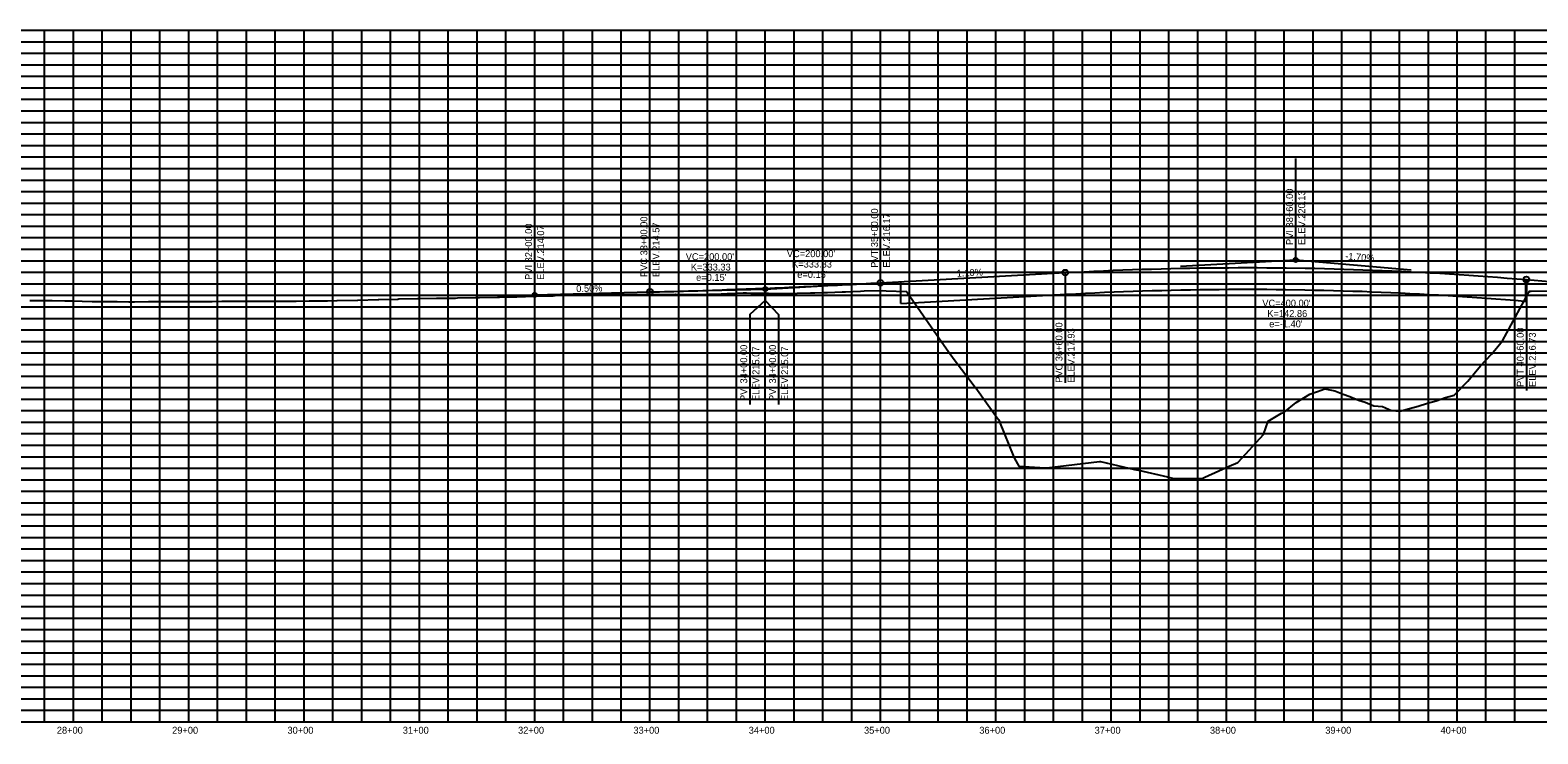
# Model space of a CAD drawing. Extents: x 1732967 to 1742744, y 374025 to 374739.
# Drawn here: x 1735020 to 1736327, y 374119 to 374730 of the extents above; entities that cross this region are included whole.
import ezdxf

# ---------------------------------------------------------------- set-up
doc = ezdxf.new("R2010")
doc.units = 0
for name, color, linetype in [('R_Axis_Annotation', 7, 'Continuous'), ('R_Draft', 7, 'Continuous'), ('R_Exist Surface', 7, 'Continuous'), ('R_Grid', 7, 'Continuous'), ('R_Grid_Minor', 7, 'Continuous'), ('R_Vert Alg', 7, 'Continuous'), ('R_Vert Alg Annot', 7, 'Continuous')]:
    doc.layers.add(name, color=color, linetype=linetype)

msp = doc.modelspace()

# ---------------------------------------------------------------- linework, layer by layer
at = {"layer": 'R_Draft'}
for p, q in [((1735774.6, 374492.6), (1735774.6, 374511.4)), ((1736316.7, 374494.5), (1736316.7, 374513.3)), ((1735774.6, 374492.6), (1735918.2, 374500.5)), ((1736315.6, 374494.6), (1736316.7, 374494.5))]:
    msp.add_line(p, q, dxfattribs=at)
msp.add_lwpolyline([(1735918.2, 374500.5), (1735926.5, 374501), (1735934.8, 374501.4), (1735943, 374501.8), (1735951.3, 374502.2), (1735959.6, 374502.5), (1735967.9, 374502.8), (1735976.1, 374503.1), (1735984.4, 374503.4), (1735992.7, 374503.7), (1736001, 374503.9), (1736009.3, 374504.1), (1736017.5, 374504.3), (1736025.8, 374504.4), (1736034.1, 374504.6), (1736042.4, 374504.7), (1736050.7, 374504.7), (1736058.9, 374504.8), (1736067.2, 374504.8), (1736075.5, 374504.8), (1736083.8, 374504.8), (1736092, 374504.8), (1736100.3, 374504.7), (1736108.6, 374504.6), (1736125.2, 374504.4), (1736133.4, 374504.2), (1736141.7, 374504), (1736150, 374503.8), (1736158.3, 374503.6), (1736166.6, 374503.3), (1736174.8, 374503.1), (1736183.1, 374502.7), (1736191.4, 374502.4), (1736199.7, 374502.1), (1736208, 374501.7), (1736216.2, 374501.3), (1736224.5, 374500.9), (1736232.8, 374500.4), (1736241.1, 374499.9), (1736249.3, 374499.4), (1736257.6, 374498.9), (1736265.9, 374498.4), (1736274.2, 374497.8), (1736282.5, 374497.2), (1736290.7, 374496.6), (1736299, 374495.9), (1736307.3, 374495.3), (1736315.6, 374494.6)], dxfattribs=at)
at = {"layer": 'R_Exist Surface'}
msp.add_lwpolyline([(1735019.5, 374495.2), (1735020.3, 374495.2), (1735021.1, 374495.2), (1735034.6, 374495.1), (1735038, 374495.1), (1735038.7, 374495.1), (1735049.8, 374494.9), (1735055.7, 374494.7), (1735056.1, 374494.7), (1735064.9, 374494.5), (1735073.4, 374494.3), (1735073.5, 374494.3), (1735077.7, 374494.3), (1735080, 374494.3), (1735089.6, 374494.1), (1735095.2, 374494.1), (1735105.1, 374493.9), (1735105.7, 374493.9), (1735110.3, 374494), (1735122.2, 374494.1), (1735122.8, 374494.1), (1735123.5, 374494.1), (1735125.5, 374494.1), (1735140, 374494.2), (1735140.6, 374494.2), (1735140.9, 374494.2), (1735155.7, 374494.3), (1735158.8, 374494.3), (1735170.9, 374494.3), (1735176.5, 374494.3), (1735177.5, 374494.3), (1735186, 374494.4), (1735195, 374494.5), (1735195.8, 374494.5), (1735196.6, 374494.5), (1735201.2, 374494.5), (1735214.1, 374494.6), (1735214.7, 374494.6), (1735216.3, 374494.6), (1735231.4, 374494.6), (1735232.1, 374494.6), (1735232.6, 374494.6), (1735246.6, 374494.6), (1735250, 374494.6), (1735250.4, 374494.6), (1735261.7, 374494.7), (1735267.9, 374494.8), (1735268, 374494.8), (1735276.9, 374494.9), (1735277.4, 374494.9), (1735285.6, 374495), (1735285.8, 374495), (1735303.5, 374495.4), (1735303.9, 374495.4), (1735321.4, 374495.9), (1735322, 374495.9), (1735338.5, 374496.3), (1735339.4, 374496.4), (1735355.5, 374496.8), (1735356.7, 374496.9), (1735372.1, 374497), (1735373.5, 374497.1), (1735388.6, 374497.2), (1735390.2, 374497.3), (1735405.9, 374497.6), (1735407.6, 374497.7), (1735409.4, 374497.7), (1735425, 374498), (1735426.8, 374498.1), (1735441.8, 374498.4), (1735456.8, 374498.8), (1735458.5, 374498.8), (1735473.3, 374499.2), (1735474.9, 374499.3), (1735489.7, 374499.7), (1735491.3, 374499.8), (1735506.4, 374500), (1735507.8, 374500), (1735523.1, 374500.3), (1735524.3, 374500.3), (1735525.3, 374500.3), (1735537.2, 374500.4), (1735538.5, 374500.4), (1735552.3, 374500.4), (1735564.3, 374500.4), (1735565.9, 374500.4), (1735578.1, 374500.4), (1735579.4, 374500.5), (1735591.2, 374500.4), (1735592.2, 374500.4), (1735604.1, 374500.4), (1735608, 374500.4), (1735608.6, 374500.5), (1735613.7, 374500.7), (1735624.1, 374501.2), (1735627, 374501.2), (1735638.1, 374501.7), (1735640.8, 374501.6), (1735644.6, 374501.5), (1735656.6, 374501.4), (1735660.1, 374501.4), (1735671.8, 374501.2), (1735681.7, 374501.3), (1735684.8, 374501.4), (1735696.4, 374501.6), (1735698.8, 374501.7), (1735700.1, 374501.7), (1735708, 374501.9), (1735711, 374502), (1735724, 374502.5), (1735726.7, 374502.6), (1735739.9, 374503.2), (1735742.8, 374503.4), (1735758.9, 374503.8), (1735761.9, 374503.5), (1735779.7, 374502.9), (1735780.6, 374501.7), (1735814.3, 374453.2), (1735817.7, 374448.3), (1735817.8, 374448.2), (1735818, 374448), (1735821.1, 374443.9), (1735839.1, 374420), (1735839.7, 374419.2), (1735858.2, 374393.3), (1735859.6, 374391.7), (1735859.7, 374391.7), (1735860.4, 374389.9), (1735872.7, 374359.3), (1735873.2, 374357.9), (1735877, 374351.3), (1735895.2, 374350.3), (1735901.8, 374349.9), (1735903.8, 374350.1), (1735946.9, 374355.4), (1735948, 374355.5), (1735977.5, 374348.5), (1735980.9, 374347.8), (1736006.1, 374342), (1736009.1, 374341.3), (1736011.4, 374340.8), (1736036.5, 374341), (1736038.4, 374341.8), (1736059.4, 374351.3), (1736066.9, 374354.7), (1736067.4, 374354.9), (1736067.7, 374355.2), (1736089.3, 374378.8), (1736093.4, 374390.4), (1736105, 374397.4), (1736107, 374397.8), (1736117.5, 374406.5), (1736129.4, 374413.7), (1736136, 374416.1), (1736142.5, 374418.5), (1736151.2, 374416.6), (1736158.2, 374413.7), (1736164.2, 374411.8), (1736171.6, 374408.7), (1736177.3, 374407), (1736184.9, 374403.7), (1736192.5, 374403.2), (1736200.3, 374399.8), (1736207.5, 374399.2), (1736215.8, 374401.4), (1736223.5, 374403.4), (1736231.4, 374406.1), (1736239.1, 374408.2), (1736247, 374410.9), (1736254.7, 374412.9), (1736266.4, 374425.1), (1736277.3, 374438.3), (1736286.9, 374448.5), (1736296.4, 374460), (1736319.1, 374501.8), (1736319.7, 374502.4), (1736319.9, 374503.3), (1736321.4, 374503.3), (1736342, 374503.6)], dxfattribs=at)
at = {"layer": 'R_Grid'}
for p, q in [((1734257.2, 374729.6), (1737057.2, 374729.6)), ((1734257.2, 374729.6), (1737057.2, 374729.6)), ((1735057.2, 374129.6), (1735057.2, 374729.6)), ((1735157.2, 374129.6), (1735157.2, 374729.6)), ((1735257.2, 374129.6), (1735257.2, 374729.6)), ((1735357.2, 374129.6), (1735357.2, 374729.6)), ((1735457.2, 374129.6), (1735457.2, 374729.6)), ((1735557.2, 374129.6), (1735557.2, 374729.6)), ((1735657.2, 374129.6), (1735657.2, 374729.6)), ((1735757.2, 374129.6), (1735757.2, 374729.6)), ((1735857.2, 374129.6), (1735857.2, 374729.6)), ((1735957.2, 374129.6), (1735957.2, 374729.6)), ((1736057.2, 374129.6), (1736057.2, 374729.6)), ((1736157.2, 374129.6), (1736157.2, 374729.6)), ((1736257.2, 374129.6), (1736257.2, 374729.6)), ((1734257.2, 374679.6), (1737057.2, 374679.6)), ((1734257.2, 374629.6), (1737057.2, 374629.6)), ((1734257.2, 374579.6), (1737057.2, 374579.6)), ((1734257.2, 374529.6), (1737057.2, 374529.6)), ((1734257.2, 374479.6), (1737057.2, 374479.6)), ((1734257.2, 374429.6), (1737057.2, 374429.6)), ((1734257.2, 374379.6), (1737057.2, 374379.6)), ((1734257.2, 374329.6), (1737057.2, 374329.6)), ((1734257.2, 374279.6), (1737057.2, 374279.6)), ((1734257.2, 374229.6), (1737057.2, 374229.6)), ((1734257.2, 374179.6), (1737057.2, 374179.6)), ((1734257.2, 374129.6), (1737057.2, 374129.6))]:
    msp.add_line(p, q, dxfattribs=at)
at = {"layer": 'R_Grid_Minor'}
for p, q in [((1735032.2, 374129.6), (1735032.2, 374729.6)), ((1735082.2, 374129.6), (1735082.2, 374729.6)), ((1735107.2, 374129.6), (1735107.2, 374729.6)), ((1735132.2, 374129.6), (1735132.2, 374729.6)), ((1735182.2, 374129.6), (1735182.2, 374729.6)), ((1735207.2, 374129.6), (1735207.2, 374729.6)), ((1735232.2, 374129.6), (1735232.2, 374729.6)), ((1735282.2, 374129.6), (1735282.2, 374729.6)), ((1735307.2, 374129.6), (1735307.2, 374729.6)), ((1735332.2, 374129.6), (1735332.2, 374729.6)), ((1735382.2, 374129.6), (1735382.2, 374729.6)), ((1735407.2, 374129.6), (1735407.2, 374729.6)), ((1735432.2, 374129.6), (1735432.2, 374729.6)), ((1735482.2, 374129.6), (1735482.2, 374729.6)), ((1735507.2, 374129.6), (1735507.2, 374729.6)), ((1735532.2, 374129.6), (1735532.2, 374729.6)), ((1735582.2, 374129.6), (1735582.2, 374729.6)), ((1735607.2, 374129.6), (1735607.2, 374729.6)), ((1735632.2, 374129.6), (1735632.2, 374729.6)), ((1735682.2, 374129.6), (1735682.2, 374729.6)), ((1735707.2, 374129.6), (1735707.2, 374729.6)), ((1735732.2, 374129.6), (1735732.2, 374729.6)), ((1735782.2, 374129.6), (1735782.2, 374729.6)), ((1735807.2, 374129.6), (1735807.2, 374729.6)), ((1735832.2, 374129.6), (1735832.2, 374729.6)), ((1735882.2, 374129.6), (1735882.2, 374729.6)), ((1735907.2, 374129.6), (1735907.2, 374729.6)), ((1735932.2, 374129.6), (1735932.2, 374729.6)), ((1735982.2, 374129.6), (1735982.2, 374729.6)), ((1736007.2, 374129.6), (1736007.2, 374729.6)), ((1736032.2, 374129.6), (1736032.2, 374729.6)), ((1736082.2, 374129.6), (1736082.2, 374729.6)), ((1736107.2, 374129.6), (1736107.2, 374729.6)), ((1736132.2, 374129.6), (1736132.2, 374729.6)), ((1736182.2, 374129.6), (1736182.2, 374729.6)), ((1736207.2, 374129.6), (1736207.2, 374729.6)), ((1736232.2, 374129.6), (1736232.2, 374729.6)), ((1736282.2, 374129.6), (1736282.2, 374729.6)), ((1736307.2, 374129.6), (1736307.2, 374729.6)), ((1734257.2, 374719.6), (1737057.2, 374719.6)), ((1734257.2, 374709.6), (1737057.2, 374709.6)), ((1734257.2, 374699.6), (1737057.2, 374699.6)), ((1734257.2, 374689.6), (1737057.2, 374689.6)), ((1734257.2, 374669.6), (1737057.2, 374669.6)), ((1734257.2, 374659.6), (1737057.2, 374659.6)), ((1734257.2, 374649.6), (1737057.2, 374649.6)), ((1734257.2, 374639.6), (1737057.2, 374639.6)), ((1734257.2, 374619.6), (1737057.2, 374619.6)), ((1734257.2, 374609.6), (1737057.2, 374609.6)), ((1734257.2, 374599.6), (1737057.2, 374599.6)), ((1734257.2, 374589.6), (1737057.2, 374589.6)), ((1734257.2, 374569.6), (1737057.2, 374569.6)), ((1734257.2, 374559.6), (1737057.2, 374559.6)), ((1734257.2, 374549.6), (1737057.2, 374549.6)), ((1734257.2, 374539.6), (1737057.2, 374539.6)), ((1734257.2, 374519.6), (1737057.2, 374519.6)), ((1734257.2, 374509.6), (1737057.2, 374509.6)), ((1734257.2, 374499.6), (1737057.2, 374499.6)), ((1734257.2, 374489.6), (1737057.2, 374489.6)), ((1734257.2, 374469.6), (1737057.2, 374469.6)), ((1734257.2, 374459.6), (1737057.2, 374459.6)), ((1734257.2, 374449.6), (1737057.2, 374449.6)), ((1734257.2, 374439.6), (1737057.2, 374439.6)), ((1734257.2, 374419.6), (1737057.2, 374419.6)), ((1734257.2, 374409.6), (1737057.2, 374409.6)), ((1734257.2, 374399.6), (1737057.2, 374399.6)), ((1734257.2, 374389.6), (1737057.2, 374389.6)), ((1734257.2, 374369.6), (1737057.2, 374369.6)), ((1734257.2, 374359.6), (1737057.2, 374359.6)), ((1734257.2, 374349.6), (1737057.2, 374349.6)), ((1734257.2, 374339.6), (1737057.2, 374339.6)), ((1734257.2, 374319.6), (1737057.2, 374319.6)), ((1734257.2, 374309.6), (1737057.2, 374309.6)), ((1734257.2, 374299.6), (1737057.2, 374299.6)), ((1734257.2, 374289.6), (1737057.2, 374289.6)), ((1734257.2, 374269.6), (1737057.2, 374269.6)), ((1734257.2, 374259.6), (1737057.2, 374259.6)), ((1734257.2, 374249.6), (1737057.2, 374249.6)), ((1734257.2, 374239.6), (1737057.2, 374239.6)), ((1734257.2, 374219.6), (1737057.2, 374219.6)), ((1734257.2, 374209.6), (1737057.2, 374209.6)), ((1734257.2, 374199.6), (1737057.2, 374199.6)), ((1734257.2, 374189.6), (1737057.2, 374189.6)), ((1734257.2, 374169.6), (1737057.2, 374169.6)), ((1734257.2, 374159.6), (1737057.2, 374159.6)), ((1734257.2, 374149.6), (1737057.2, 374149.6)), ((1734257.2, 374139.6), (1737057.2, 374139.6))]:
    msp.add_line(p, q, dxfattribs=at)
at = {"layer": 'R_Vert Alg'}
for p, q in [((1735757.2, 374510.5), (1735917.2, 374519.3)), ((1736317.2, 374513.3), (1736337.2, 374511.6)), ((1735457.2, 374500), (1735557.2, 374502.5))]:
    msp.add_line(p, q, dxfattribs=at)
for points in [[(1735917.2, 374519.3), (1735925.5, 374519.7), (1735933.8, 374520.1), (1735942.2, 374520.5), (1735950.5, 374520.9), (1735958.8, 374521.3), (1735967.2, 374521.6), (1735975.5, 374521.9), (1735983.8, 374522.2), (1735992.2, 374522.4), (1736000.5, 374522.6), (1736008.8, 374522.8), (1736017.2, 374523), (1736025.5, 374523.2), (1736033.8, 374523.3), (1736042.2, 374523.4), (1736050.5, 374523.5), (1736058.8, 374523.5), (1736067.2, 374523.6), (1736075.5, 374523.6), (1736083.8, 374523.6), (1736092.2, 374523.5), (1736100.5, 374523.5), (1736108.8, 374523.4), (1736125.5, 374523.1), (1736133.8, 374523), (1736142.2, 374522.8), (1736150.5, 374522.6), (1736158.8, 374522.3), (1736167.2, 374522.1), (1736175.5, 374521.8), (1736183.8, 374521.5), (1736192.2, 374521.2), (1736200.5, 374520.8), (1736208.8, 374520.4), (1736217.2, 374520), (1736225.5, 374519.6), (1736233.8, 374519.1), (1736242.2, 374518.7), (1736250.5, 374518.2), (1736258.8, 374517.6), (1736267.2, 374517.1), (1736275.5, 374516.5), (1736283.8, 374515.9), (1736292.2, 374515.3), (1736300.5, 374514.6), (1736308.8, 374514), (1736317.2, 374513.3)], [(1735557.2, 374502.5), (1735561.3, 374502.6), (1735565.5, 374502.7), (1735569.7, 374502.8), (1735573.8, 374502.9), (1735578, 374503), (1735582.2, 374503.1), (1735586.3, 374503.3), (1735590.5, 374503.4), (1735594.7, 374503.5), (1735598.8, 374503.6), (1735603, 374503.8), (1735607.2, 374503.9), (1735611.3, 374504), (1735615.5, 374504.2), (1735619.7, 374504.3), (1735623.8, 374504.5), (1735628, 374504.6), (1735632.2, 374504.8), (1735636.3, 374504.9), (1735640.5, 374505.1), (1735644.7, 374505.2), (1735648.8, 374505.4), (1735653, 374505.5), (1735661.3, 374505.9), (1735665.5, 374506.1), (1735669.7, 374506.2), (1735673.8, 374506.4), (1735678, 374506.6), (1735682.2, 374506.8), (1735686.3, 374506.9), (1735690.5, 374507.1), (1735694.7, 374507.3), (1735698.8, 374507.5), (1735703, 374507.7), (1735707.2, 374507.9), (1735711.3, 374508.1), (1735715.5, 374508.3), (1735719.7, 374508.5), (1735723.8, 374508.7), (1735728, 374508.9), (1735732.2, 374509.1), (1735736.3, 374509.4), (1735740.5, 374509.6), (1735744.7, 374509.8), (1735748.8, 374510), (1735753, 374510.2), (1735757.2, 374510.5)]]:
    msp.add_lwpolyline(points, dxfattribs=at)
at = {"layer": 'R_Vert Alg Annot'}
for p, q in [((1736117.2, 374540.3), (1736117.2, 374618.3)), ((1735757.2, 374520.5), (1735757.2, 374598.5)), ((1735457.2, 374510), (1735457.2, 374588)), ((1735557.2, 374512.5), (1735557.2, 374590.5)), ((1736117.2, 374530.3), (1736117.2, 374540.3)), ((1735757.2, 374510.5), (1735757.2, 374520.5)), ((1736017.2, 374524.8), (1736117.2, 374530.3)), ((1736117.2, 374530.3), (1736217.2, 374521.8)), ((1735457.2, 374500), (1735457.2, 374510)), ((1735557.2, 374502.5), (1735557.2, 374512.5)), ((1735657.2, 374505), (1735707.2, 374507.7)), ((1735917.2, 374519.3), (1735917.2, 374509.3)), ((1735917.2, 374509.3), (1735917.2, 374423.8)), ((1736317.2, 374513.3), (1736317.2, 374503.3)), ((1735607.2, 374503.7), (1735657.2, 374505)), ((1735657.2, 374505), (1735657.2, 374495)), ((1736317.2, 374503.3), (1736317.2, 374417))]:
    msp.add_line(p, q, dxfattribs=at)
for points in [[(1735657.2, 374495), (1735643.7, 374482.9), (1735643.7, 374404.9)], [(1735657.2, 374495), (1735668.7, 374482.9), (1735668.7, 374404.9)]]:
    msp.add_lwpolyline(points, dxfattribs=at)
for centre, radius in [((1735917.2, 374519.3), 2.5), ((1736117.2, 374530.3), 1.85), ((1735657.2, 374505), 1.85), ((1735757.2, 374510.5), 2.5), ((1736317.2, 374513.3), 2.5), ((1735457.2, 374500), 1.85), ((1735557.2, 374502.5), 2.5)]:
    msp.add_circle(centre, radius, dxfattribs=at)

# ---------------------------------------------------------------- texts
at = {"layer": 'R_Axis_Annotation'}
for s, p in [('28+00', (1735042.8, 374119.3)), ('29+00', (1735142.8, 374119.3)), ('30+00', (1735242.8, 374119.3)), ('31+00', (1735342.8, 374119.3)), ('32+00', (1735442.8, 374119.3)), ('33+00', (1735542.8, 374119.3)), ('34+00', (1735642.8, 374119.3)), ('35+00', (1735742.8, 374119.3)), ('36+00', (1735842.8, 374119.3)), ('37+00', (1735942.8, 374119.3)), ('38+00', (1736042.8, 374119.3)), ('39+00', (1736142.8, 374119.3)), ('40+00', (1736242.8, 374119.3))]:
    msp.add_text(s, height=6, dxfattribs=at).set_placement(p)
at = {"layer": 'R_Vert Alg Annot'}
for s, rotation, p in [('PVI 38+60.00', 90, (1736114.9, 374543.3)), ('ELEV.220.13', 90, (1736125.4, 374543.3)), ('PVT 35+00.00', 90, (1735754.9, 374523.5)), ('PVI 32+00.00', 90, (1735454.9, 374513)), ('ELEV.214.07', 90, (1735465.4, 374513)), ('PVC 33+00.00', 90, (1735554.9, 374515.5)), ('ELEV.214.57', 90, (1735565.4, 374515.5)), ('ELEV.216.17', 90, (1735765.4, 374523.5)), ('-1.70%', 355.1415, (1736159.9, 374530.8)), ('1.10%', 3.1481, (1735823.3, 374515.6)), ('0.50%', 1.4321, (1735493.3, 374502.4)), ('PVC 36+60.00', 90, (1735914.9, 374423.7)), ('ELEV.217.93', 90, (1735925.4, 374423.7)), ('PVT 40+60.00', 90, (1736314.9, 374420.1)), ('PVI 34+00.00', 90, (1735641.5, 374407.9)), ('ELEV.215.07', 90, (1735652, 374407.9)), ('PVI 34+00.00', 90, (1735666.5, 374407.9)), ('ELEV.215.07', 90, (1735677, 374407.9)), ('ELEV.216.73', 90, (1736325.4, 374420.1))]:
    msp.add_text(s, height=6, rotation=rotation, dxfattribs=at).set_placement(p)
for s, p in [("VC=200.00'", (1735588.2, 374530.1)), ("VC=200.00'", (1735675.9, 374532.7)), ('K=333.33', (1735592.6, 374521.1)), ('K=333.33', (1735680.4, 374523.7)), ("e=0.15'", (1735684.9, 374514.7)), ("e=0.15'", (1735597.2, 374512.1)), ("VC=400.00'", (1736088.2, 374489.8)), ('K=142.86', (1736092.6, 374480.8)), ("e=-1.40'", (1736094.2, 374471.8))]:
    msp.add_text(s, height=6, dxfattribs=at).set_placement(p)

doc.saveas('drawing.dxf')
